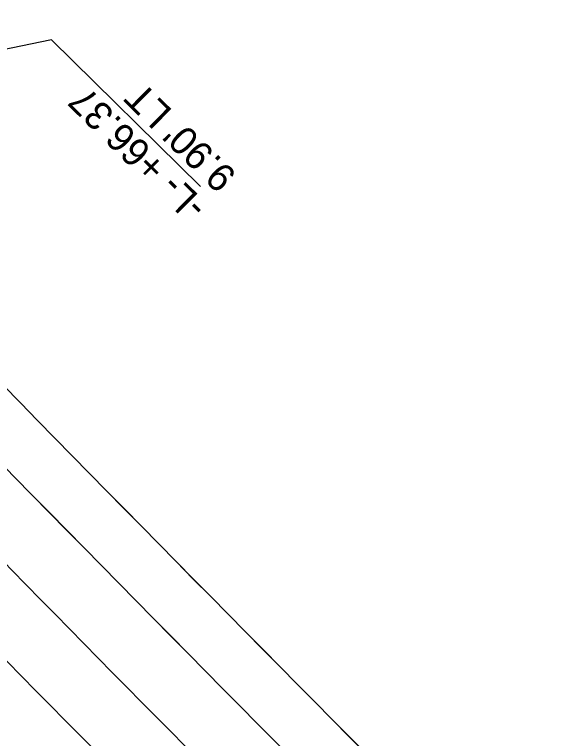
# Model space of a CAD drawing. Extents: x 1262642 to 1268358, y 767825 to 773481.
# Drawn here: x 1266941.8 to 1267038.7, y 772031 to 772160.2 of the extents above; entities that cross this region are included whole.
import ezdxf

# ---------------------------------------------------------------- set-up
doc = ezdxf.new("R2010")
doc.units = 0
for name, color, linetype in [('Prop Conc 1ft 6in Curb and Gutter', 7, 'Continuous'), ('Prop Dimension Text', 7, 'Continuous'), ('Prop EOT', 7, 'Continuous'), ('Prop Horizontal Alignment', 7, 'Continuous'), ('Prop Lane Lines', 7, 'Continuous'), ('Prop Paved Shoulder', 7, 'Continuous'), ('Prop Shade Light', 7, 'Continuous')]:
    doc.layers.add(name, color=color, linetype=linetype)

msp = doc.modelspace()

# ---------------------------------------------------------------- linework, layer by layer
at = {"layer": 'Prop Conc 1ft 6in Curb and Gutter'}
msp.add_arc((1275047.31, 780021.23), 11414.25, 223.957867, 225.419319, dxfattribs=at)
at = {"layer": 'Prop Dimension Text'}
msp.add_line((1266974.97, 772129.5), (1266948.39, 772155.69), dxfattribs=at)
msp.add_lwpolyline([(1266948.39, 772155.69), (1266809.22, 772126.93)], dxfattribs=at)
at = {"layer": 'Prop EOT'}
for radius, start, end in [(11349, 223.976844, 225.401912), (11415, 224.252026, 225.404319), (11439, 224.175182, 225.443384)]:
    msp.add_arc((1275047.31, 780021.23), radius, start, end, dxfattribs=at)
at = {"layer": 'Prop Horizontal Alignment'}
msp.add_arc((1275047.31, 780021.23), 11400, 222.993587, 225.404319, dxfattribs=at)
at = {"layer": 'Prop Lane Lines'}
for radius, start, end in [(11427, 222.993587, 225.36373), (11361, 224.221214, 225.404319), (11373, 224.221214, 225.404319), (11385, 224.221214, 225.404319)]:
    msp.add_arc((1275047.31, 780021.23), radius, start, end, dxfattribs=at)
at = {"layer": 'Prop Paved Shoulder'}
for radius, start, end in [(11339, 223.976889, 225.401912), (11449, 223.936318, 225.443384)]:
    msp.add_arc((1275047.31, 780021.23), radius, start, end, dxfattribs=at)
at = {"layer": 'Prop Shade Light'}
for centre, radius, start, end in [((1275047.31, 780021.22), 11339, 223.976889, 225.401893), ((1275047.31, 780021.22), 11349, 223.976844, 225.401912), ((1275047.31, 780021.23), 11449, 223.936318, 225.443367), ((1275047.31, 780021.23), 11439, 224.175182, 225.443384)]:
    msp.add_arc(centre, radius, start, end, dxfattribs=at)

# ---------------------------------------------------------------- texts
at = {"layer": 'Prop Dimension Text'}
for s, p in [("9.90' LT", (1266981.65, 772131.64)), ('-L- +66.37', (1266976.39, 772126.29))]:
    msp.add_text(s, height=5, rotation=135.4239, dxfattribs=at).set_placement(p)

doc.saveas('drawing.dxf')
